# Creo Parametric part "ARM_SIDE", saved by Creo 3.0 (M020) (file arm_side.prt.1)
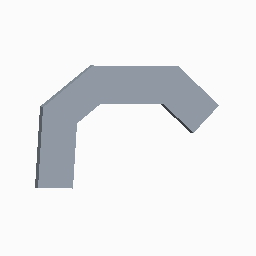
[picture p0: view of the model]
Units: millimeter Newton Second (mmNs); MM, TONNE, SECS

Created from: MMNS_PART_SOLID.PRT

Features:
  1. datum plane "RIGHT"
  2. datum plane "TOP"
  3. datum plane "FRONT"
  4. coordinate system
  5. sketch "Sketch 1"
  6. extrusion "Extrude 1"

Surfaces: 15 plane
